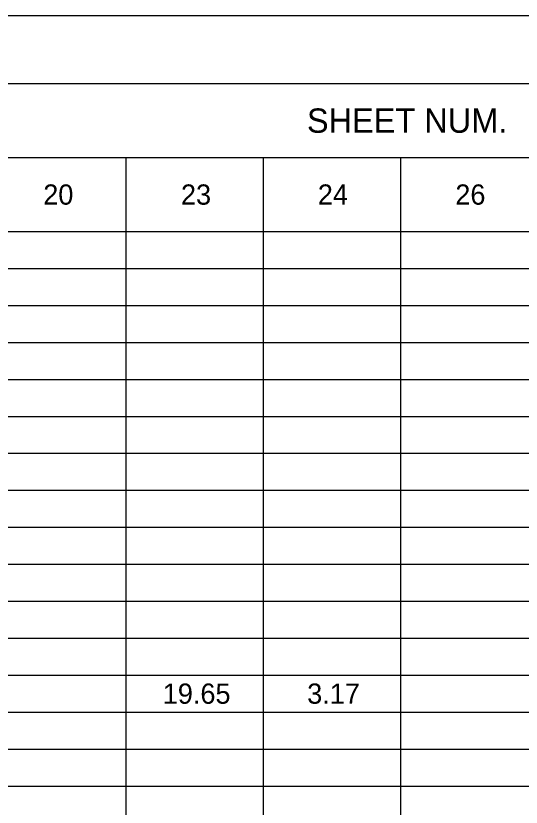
# Model space of a CAD drawing. Extents: x 0 to 34, y 0 to 22.
# Drawn here: x 3.73 to 7.45, y 16.17 to 22 of the extents above; entities that cross this region are included whole.
import ezdxf

# ---------------------------------------------------------------- set-up
doc = ezdxf.new("R2010")
doc.units = 0
for name, color, linetype in [('Default', 7, 'Continuous'), ('SH_Border', 7, 'Continuous'), ('SH_Cut_Line', 7, 'Continuous')]:
    doc.layers.add(name, color=color, linetype=linetype)

msp = doc.modelspace()

# ---------------------------------------------------------------- linework, layer by layer
at = {"layer": 'Default'}
for p, q in [((1.5, 21.5), (6.5617, 21.5)), ((6.5617, 21.5), (7.574, 21.5)), ((1.5, 20.9549), (6.5617, 20.9549)), ((4.537, 20.9549), (4.537, 20.6823)), ((5.5494, 20.9549), (5.5494, 20.6823)), ((6.5617, 20.9549), (7.574, 20.9549)), ((6.5617, 20.9549), (6.5617, 20.6823)), ((4.537, 20.6823), (4.537, 20.4098)), ((5.5494, 20.6823), (5.5494, 20.4098)), ((6.5617, 20.6823), (6.5617, 20.4098)), ((1.5, 20.4098), (6.5617, 20.4098)), ((4.537, 20.4098), (4.537, 20.1372)), ((5.5494, 20.4098), (5.5494, 20.1372)), ((6.5617, 20.4098), (7.574, 20.4098)), ((6.5617, 20.4098), (6.5617, 20.1372)), ((1.5, 20.1372), (6.5617, 20.1372)), ((4.537, 20.1372), (4.537, 18.7745)), ((5.5494, 20.1372), (5.5494, 18.7745)), ((6.5617, 20.1372), (7.574, 20.1372)), ((6.5617, 20.1372), (6.5617, 18.7745)), ((1.5, 19.8647), (6.5617, 19.8647)), ((6.5617, 19.8647), (7.574, 19.8647)), ((1.5, 19.5921), (6.5617, 19.5921)), ((6.5617, 19.5921), (7.574, 19.5921)), ((1.5, 19.3196), (6.5617, 19.3196)), ((6.5617, 19.3196), (7.574, 19.3196)), ((1.5, 19.047), (6.5617, 19.047)), ((6.5617, 19.047), (7.574, 19.047)), ((1.5, 18.7745), (6.5617, 18.7745)), ((4.537, 18.7745), (4.537, 18.2294)), ((5.5494, 18.7745), (5.5494, 18.2294)), ((6.5617, 18.7745), (7.574, 18.7745)), ((6.5617, 18.7745), (6.5617, 18.2294)), ((1.5, 18.5019), (6.5617, 18.5019)), ((6.5617, 18.5019), (7.574, 18.5019)), ((1.5, 18.2294), (6.5617, 18.2294)), ((4.537, 18.2294), (4.537, 17.9568)), ((5.5494, 18.2294), (5.5494, 17.9568)), ((6.5617, 18.2294), (7.574, 18.2294)), ((6.5617, 18.2294), (6.5617, 17.9568)), ((1.5, 17.9568), (6.5617, 17.9568)), ((4.537, 17.9568), (4.537, 17.6843)), ((5.5494, 17.9568), (5.5494, 17.6843)), ((6.5617, 17.9568), (7.574, 17.9568)), ((6.5617, 17.9568), (6.5617, 17.6843)), ((1.5, 17.6843), (6.5617, 17.6843)), ((4.537, 17.6843), (4.537, 17.4117)), ((5.5494, 17.6843), (5.5494, 17.4117)), ((6.5617, 17.6843), (7.574, 17.6843)), ((6.5617, 17.6843), (6.5617, 17.4117)), ((1.5, 17.4117), (6.5617, 17.4117)), ((4.537, 17.4117), (4.537, 17.1391)), ((5.5494, 17.4117), (5.5494, 17.1391)), ((6.5617, 17.4117), (7.574, 17.4117)), ((6.5617, 17.4117), (6.5617, 17.1391)), ((1.5, 17.1391), (6.5617, 17.1391)), ((4.537, 17.1391), (4.537, 16.8666)), ((5.5494, 17.1391), (5.5494, 16.8666)), ((6.5617, 17.1391), (7.574, 17.1391)), ((6.5617, 17.1391), (6.5617, 16.8666)), ((1.5, 16.8666), (6.5617, 16.8666)), ((4.537, 16.8666), (4.537, 16.3215)), ((5.5494, 16.8666), (5.5494, 16.3215)), ((6.5617, 16.8666), (7.574, 16.8666)), ((6.5617, 16.8666), (6.5617, 16.3215)), ((1.5, 16.594), (6.5617, 16.594)), ((6.5617, 16.594), (7.574, 16.594)), ((1.5, 16.3215), (6.5617, 16.3215)), ((4.537, 16.3215), (4.537, 16.0489)), ((5.5494, 16.3215), (5.5494, 16.0489)), ((6.5617, 16.3215), (7.574, 16.3215)), ((6.5617, 16.3215), (6.5617, 16.0489))]:
    msp.add_line(p, q, dxfattribs=at)
at = {"layer": 'SH_Border'}
msp.add_lwpolyline([(1.5, 21.5), (33.5, 21.5), (33.5, 0.5), (1.5, 0.5)], close=True, dxfattribs=at)
at = {"layer": 'SH_Cut_Line'}
msp.add_lwpolyline([(0, 0), (34, 0), (34, 22), (0, 22)], close=True, dxfattribs=at)

# ---------------------------------------------------------------- texts
at = {"layer": 'Default'}
for s, height, p in [('SHEET NUM.', 0.17911, (5.8711, 21.1379)), ('20', 0.14926, (3.9273, 20.6077)), ('23', 0.14926, (4.9424, 20.6077)), ('24', 0.14926, (5.9513, 20.6077)), ('26', 0.14926, (6.9648, 20.6077)), ('19.65', 0.14926, (4.8082, 16.9282)), ('3.17', 0.14926, (5.8728, 16.9282))]:
    msp.add_text(s, height=height, dxfattribs=at).set_placement(p)

doc.saveas('drawing.dxf')
